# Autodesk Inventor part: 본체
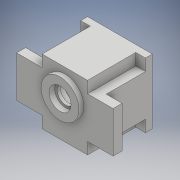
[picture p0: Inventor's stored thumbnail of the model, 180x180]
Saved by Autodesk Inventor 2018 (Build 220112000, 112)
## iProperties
Created: 2020-07
Part Number: 본체
Material: 일반
Document SubType Name: Modeling
Designer: admin
Density: 1 g/cm^3
Appearance: 기본값
Author: admin
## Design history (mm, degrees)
sketch "스케치1"
  geometry: L1 (98, 0)-(-98, 0) reference; L2 (0, -65.8)-(0, 65.8) reference; L3 (70, 0)-(70, 30); L4 (70, 30)-(33, 30); L5 (33, 30)-(33, 47); L6 (33, 47)-(-33, 47); L7 (-33, 47)-(-33, 30); L8 (-33, 30)-(-70, 30); L9 (-70, 30)-(-70, 0); L10 (70, 0)-(70, -30); L11 (70, -30)-(33, -30); L12 (33, -30)-(33, -47); L13 (33, -47)-(-33, -47); L14 (-33, -47)-(-33, -30); L15 (-33, -30)-(-70, -30); L16 (-70, -30)-(-70, 0); 1 further point
  constraints: 28 end point, 8 symmetric about line, 5 perpendicular, 2 point on line, 2 vertical
  dimensions: "d0" = 30 distance of L3.start L3.end; "d1" = 47 distance between parallel lines of L1 L6; "d2" = 140 distance between parallel lines of L9 L3; "d3" = 66 distance of L5.end L6.end
extrude "돌출1" new body sketch "스케치1" distance "d4" = 13; taper "d5" = 0 deg
sketch "스케치2"
  geometry: L1 (-98, 0)-(98, 0) reference; L2 (0, -65.8)-(0, 65.8) reference; C1 r 27.5 at (0, 11); 1 further point
  constraints: 1 centre point, 1 point on line
  dimensions: "d6" = 55 diameter of C1; "d7" = 11 distance from line of L1 C1.centre
extrude "돌출2" join sketch "스케치2" distance "d8" = 7; taper "d9" = 0 deg
sketch "스케치3"
  geometry: L1 (-98, 0)-(98, 0) reference; L2 (0, 65.8)-(0, -65.8) reference; L3 (47, -47)-(-47, -47); L4 (-47, -47)-(-47, 47); L5 (-47, 47)-(47, 47); L6 (47, 47)-(47, -47); L7 (47, -47)-(-47, 47); L8 (-47, -47)-(47, 47); 1 further point
  constraints: 12 end point, 2 midpoint, 2 parallel, 1 horizontal, 1 perpendicular
  dimensions: "d10" = 94 distance of L4.end L5.end; "d11" = 94 distance of L3.end L4.end
extrude "돌출3" join sketch "스케치3" distance "d12" = 67; taper "d13" = 0 deg
sketch "스케치5"
  geometry: L1 (33, 30)-(47, 30) reference; L2 (47, 30)-(47, 47) reference; L3 (47, 47)-(33, 47) reference; L4 (33, 47)-(33, 30) reference; L5 (-98, 0)-(98, 0) reference; L6 (0, -65.8)-(0, 65.8) reference; L7 (33, 30)-(47, 30) reference; L8 (33, 47)-(33, 30); L9 (33, 30)-(47, 30); L10 (47, 30)-(47, 47); L11 (47, 30)-(70, 30) reference; L12 (33, 47)-(33, 30) reference; L13 (47, 47)-(33, 47); L14 (-33, 47)-(-33, 30); L15 (-47, 47)-(-33, 47); L16 (-47, 30)-(-47, 47); L17 (-33, 30)-(-47, 30); L18 (47, -30)-(47, -47); L19 (47, -47)-(33, -47); L20 (47, -30)-(47, -47); L21 (47, -47)-(33, -47); L22 (33, -47)-(33, -30); L23 (33, -30)-(47, -30); L24 (33, -47)-(33, -30); L25 (33, -30)-(47, -30); L26 (-33, -30)-(-47, -30); L27 (-33, -47)-(-33, -30); L28 (-47, -47)-(-33, -47); L29 (-47, -30)-(-47, -47); 1 further point
  constraints: 40 end point, 12 symmetric about line, 3 perpendicular, 1 collinear
extrude "돌출4" cut sketch "스케치5" distance "d14" = 70; taper "d15" = 0 deg
sketch "스케치6"
  geometry: L1 (-98, 0)-(98, 0) reference; L2 (0, 65.8)-(0, -65.8) reference; C1 r 43 at (0, 0); 1 further point
  constraints: 1 centre point, 1 coincident
  dimensions: "d16" = 86 diameter of C1
extrude "돌출5" cut sketch "스케치6" distance "d17" = 9; taper "d18" = 0 deg
sketch "스케치7"
  geometry: C1 r 40 at (0, 0); 1 further point
  constraints: 1 centre point, 1 coincident
  dimensions: "d19" = 80 diameter of C1
extrude "돌출6" cut sketch "스케치7" distance "d20" = 62; taper "d21" = 0 deg
sketch "스케치8"
  geometry: L1 (-98, 0)-(98, 0) reference; L2 (0, 65.8)-(0, -65.8) reference; A1 r 21 centre (0, -11) between (-8.978, 7.984) and (8.978, 7.984); A2 r 15 centre (0, 20) between (8.978, 7.984) and (-8.978, 7.984); 1 further point
  constraints: 4 point on circle, 2 centre point, 2 point on line
  dimensions: "d22" = 30 diameter of A2; "d23" = 42 diameter of A1; "d24" = 11 distance from line of L1 A1.centre; "d25" = 20 distance from line of L1 A2.centre
extrude "돌출7" join sketch "스케치8" distance "d26" = 7; taper "d27" = 0 deg
sketch "스케치9"
  geometry: C1 r 40 at (0, 0) reference; C2 r 11 at (0, 20); A1 r 15 centre (0, 20) between (8.978, 7.984) and (-8.978, 7.984) reference; A2 r 21 centre (0, -11) between (-8.978, 7.984) and (8.978, 7.984) reference; 1 further point
  constraints: 1 centre point, 1 coincident
  dimensions: "d28" = 22 diameter of C2
extrude "돌출8" cut sketch "스케치9" distance "d29" = 7; taper "d30" = 0 deg
sketch "스케치10"
  geometry: C1 r 11 at (0, 0) reference; C2 r 9.5 at (0, 0); 1 further point
  constraints: 1 centre point, 1 coincident
  dimensions: "d31" = 19 diameter of C2
extrude "돌출9" cut sketch "스케치10" distance "d32" = 3; taper "d33" = 0 deg
sketch "스케치11"
  geometry: L1 (-24.4, 0)-(97.4, 0) reference; L2 (0, -65.8)-(0, 65.8) reference; L3 (-7, 38.5)-(-7, -16.5) reference; L4 (16, -7.984)-(16, 32) reference; L5 (-27.789, 11)-(37.16, 11); L6 (-7, 27)-(1.3, 27); L7 (1.3, 27)-(1.3, 23.5); L8 (1.3, 23.5)-(6, 23.5); L9 (6, 23.5)-(6, 28.5); L10 (9, 40)-(9, -40) reference; L11 (6, 28.5)-(16, 28.5); L12 (-7, 27)-(-7, 11); L13 (-7, 11)-(16, 11); L14 (16, 11)-(16, 28.5); 1 further point
  constraints: 18 end point, 5 perpendicular, 5 point on line, 1 horizontal, 1 midpoint, 1 parallel
  dimensions: "d34" = 11 distance between parallel lines of L1 L5; "d35" = 32 diameter of L6 L5; "d36" = 25 diameter of L8 L5; "d37" = 35 diameter of L11 L5; "d38" = 8.3 distance of L6.start L6.end; "d39" = 10 distance of L9.end L11.end
revolve "회전1" sketch "스케치11" stored, may be unused: angle "d40" = 90 deg
sketch "스케치12"
  geometry: L1 (-98, 0)-(98, 0) reference; L2 (0, 65.8)-(0, -65.8) reference; L3 (39.799, 4)-(35.777, 4); L4 (39.799, -4)-(35.777, -4); L5 (-39.799, -4)-(-35.777, -4); L6 (-39.799, 4)-(-35.777, 4); A1 r 36 centre (0, 0) between (36, 0) and (35.777, 4); A2 r 4 centre (36, 0) between (36, 4) and (36, -4); A3 r 40 centre (0, 0) between (39.799, -4) and (39.799, 4); A4 r 4 centre (-36, 0) between (-36, -4) and (-36, 4); A5 r 40 centre (0, 0) between (-39.799, 4) and (-39.799, -4); 1 further point
  constraints: 11 point on circle, 8 end point, 7 symmetric about line, 5 centre point, 5 point on line, 2 coincident, 2 horizontal, 2 tangent, 2 other
  dimensions: "d41" = 72 diameter of A1; "d42" = 8 diameter of A2; "d44" = 40 radius of A3
extrude "돌출10" join sketch "스케치12" stored distance "d45" = 0; taper "d46" = 0 deg
node "솔리드1"
node "투영된 루프1"
node "투영된 루프2"
node "투영된 루프3"
